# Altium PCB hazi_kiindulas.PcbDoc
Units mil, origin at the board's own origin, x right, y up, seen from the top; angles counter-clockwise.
Board outline 3628.74 x 2378.74 mil, 2 copper layers (Top Layer, Bottom Layer); 31 components, 39 nets, 235 pads, 42 vias.
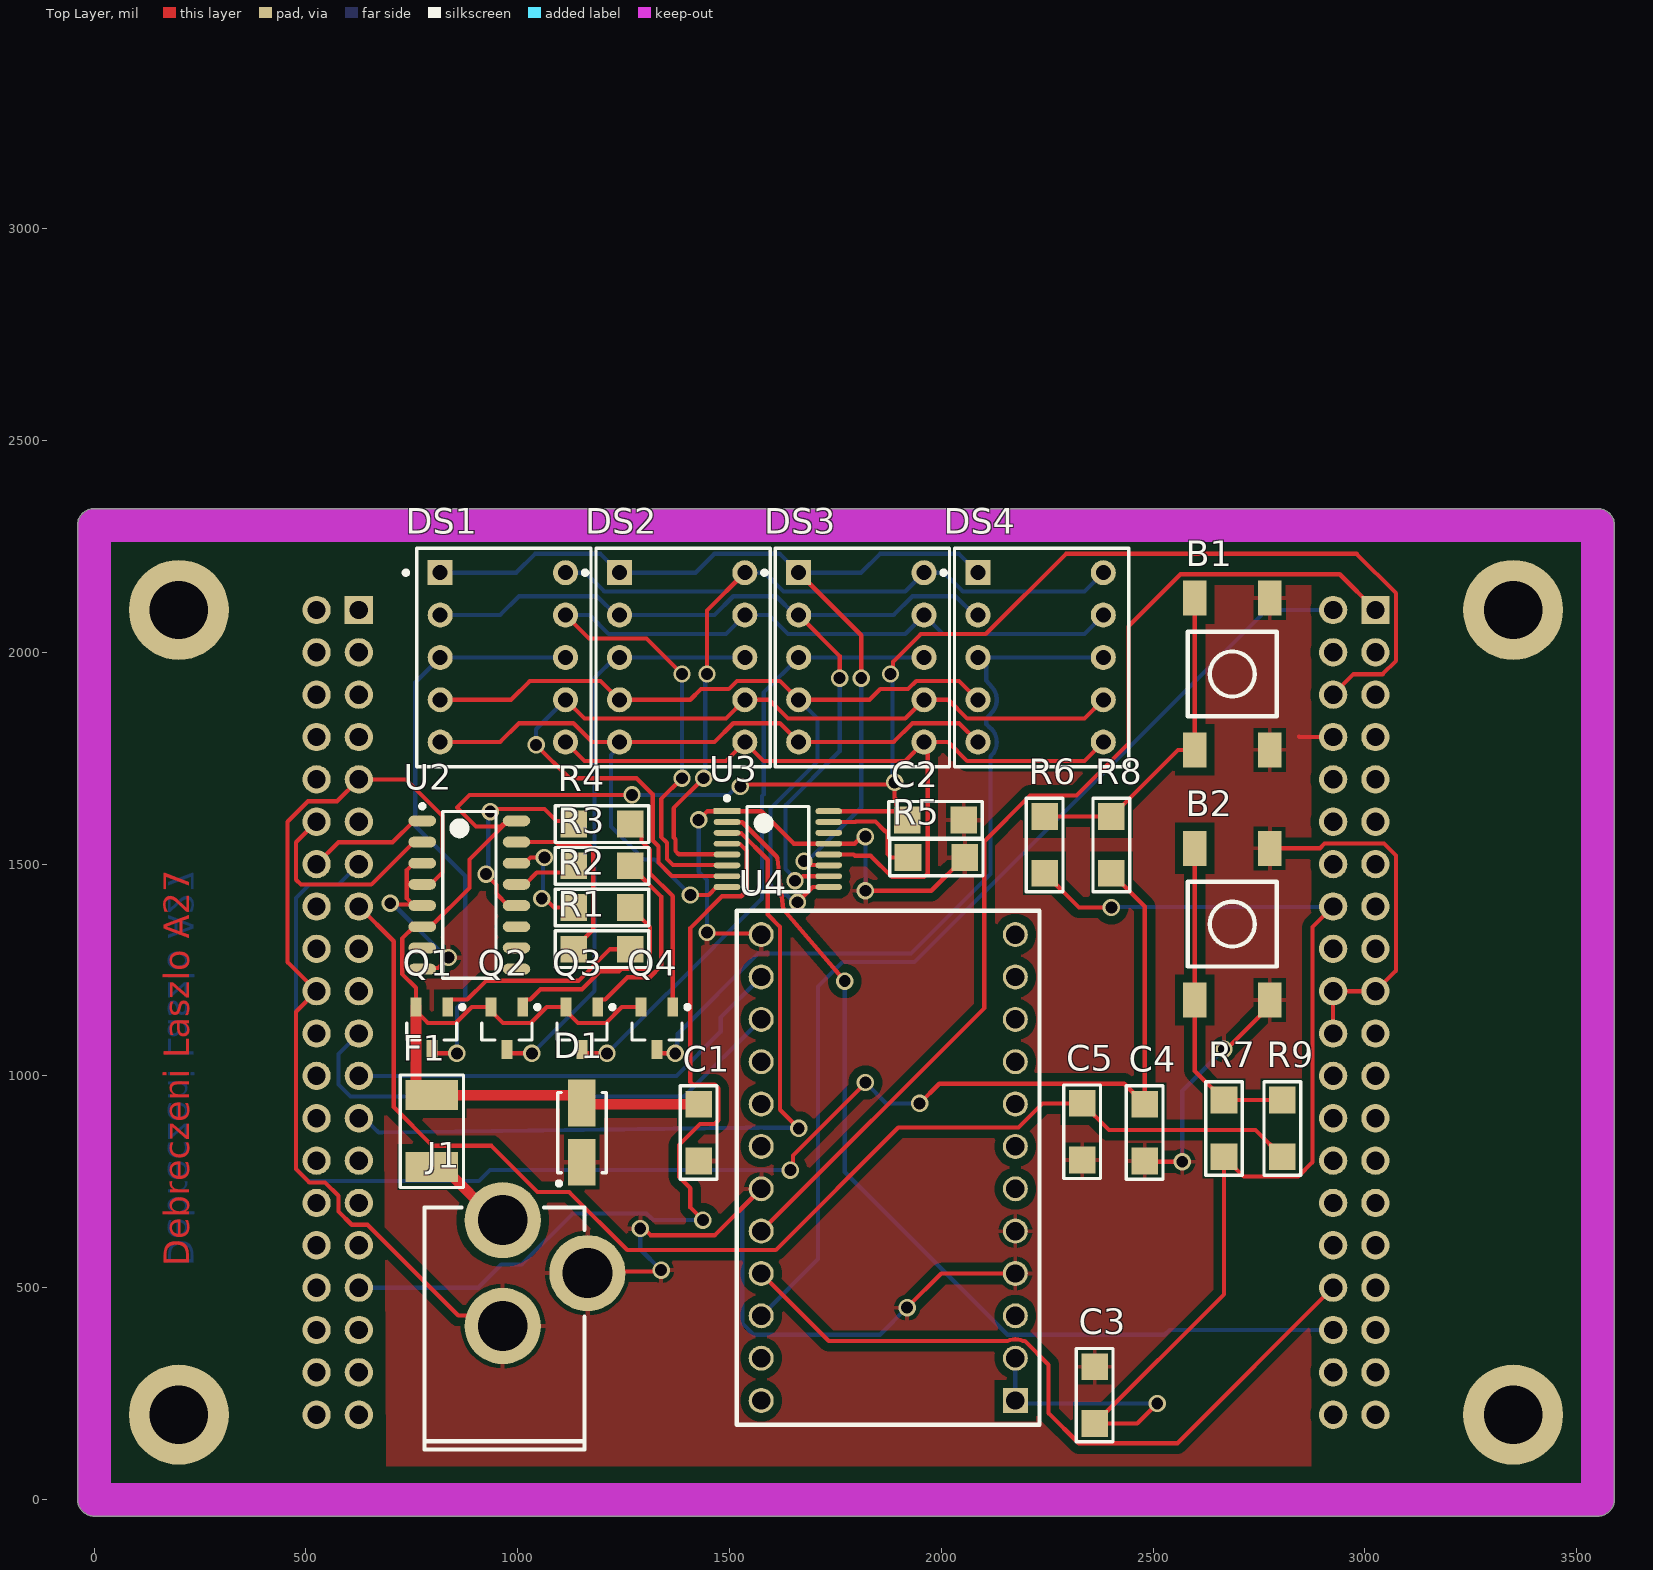
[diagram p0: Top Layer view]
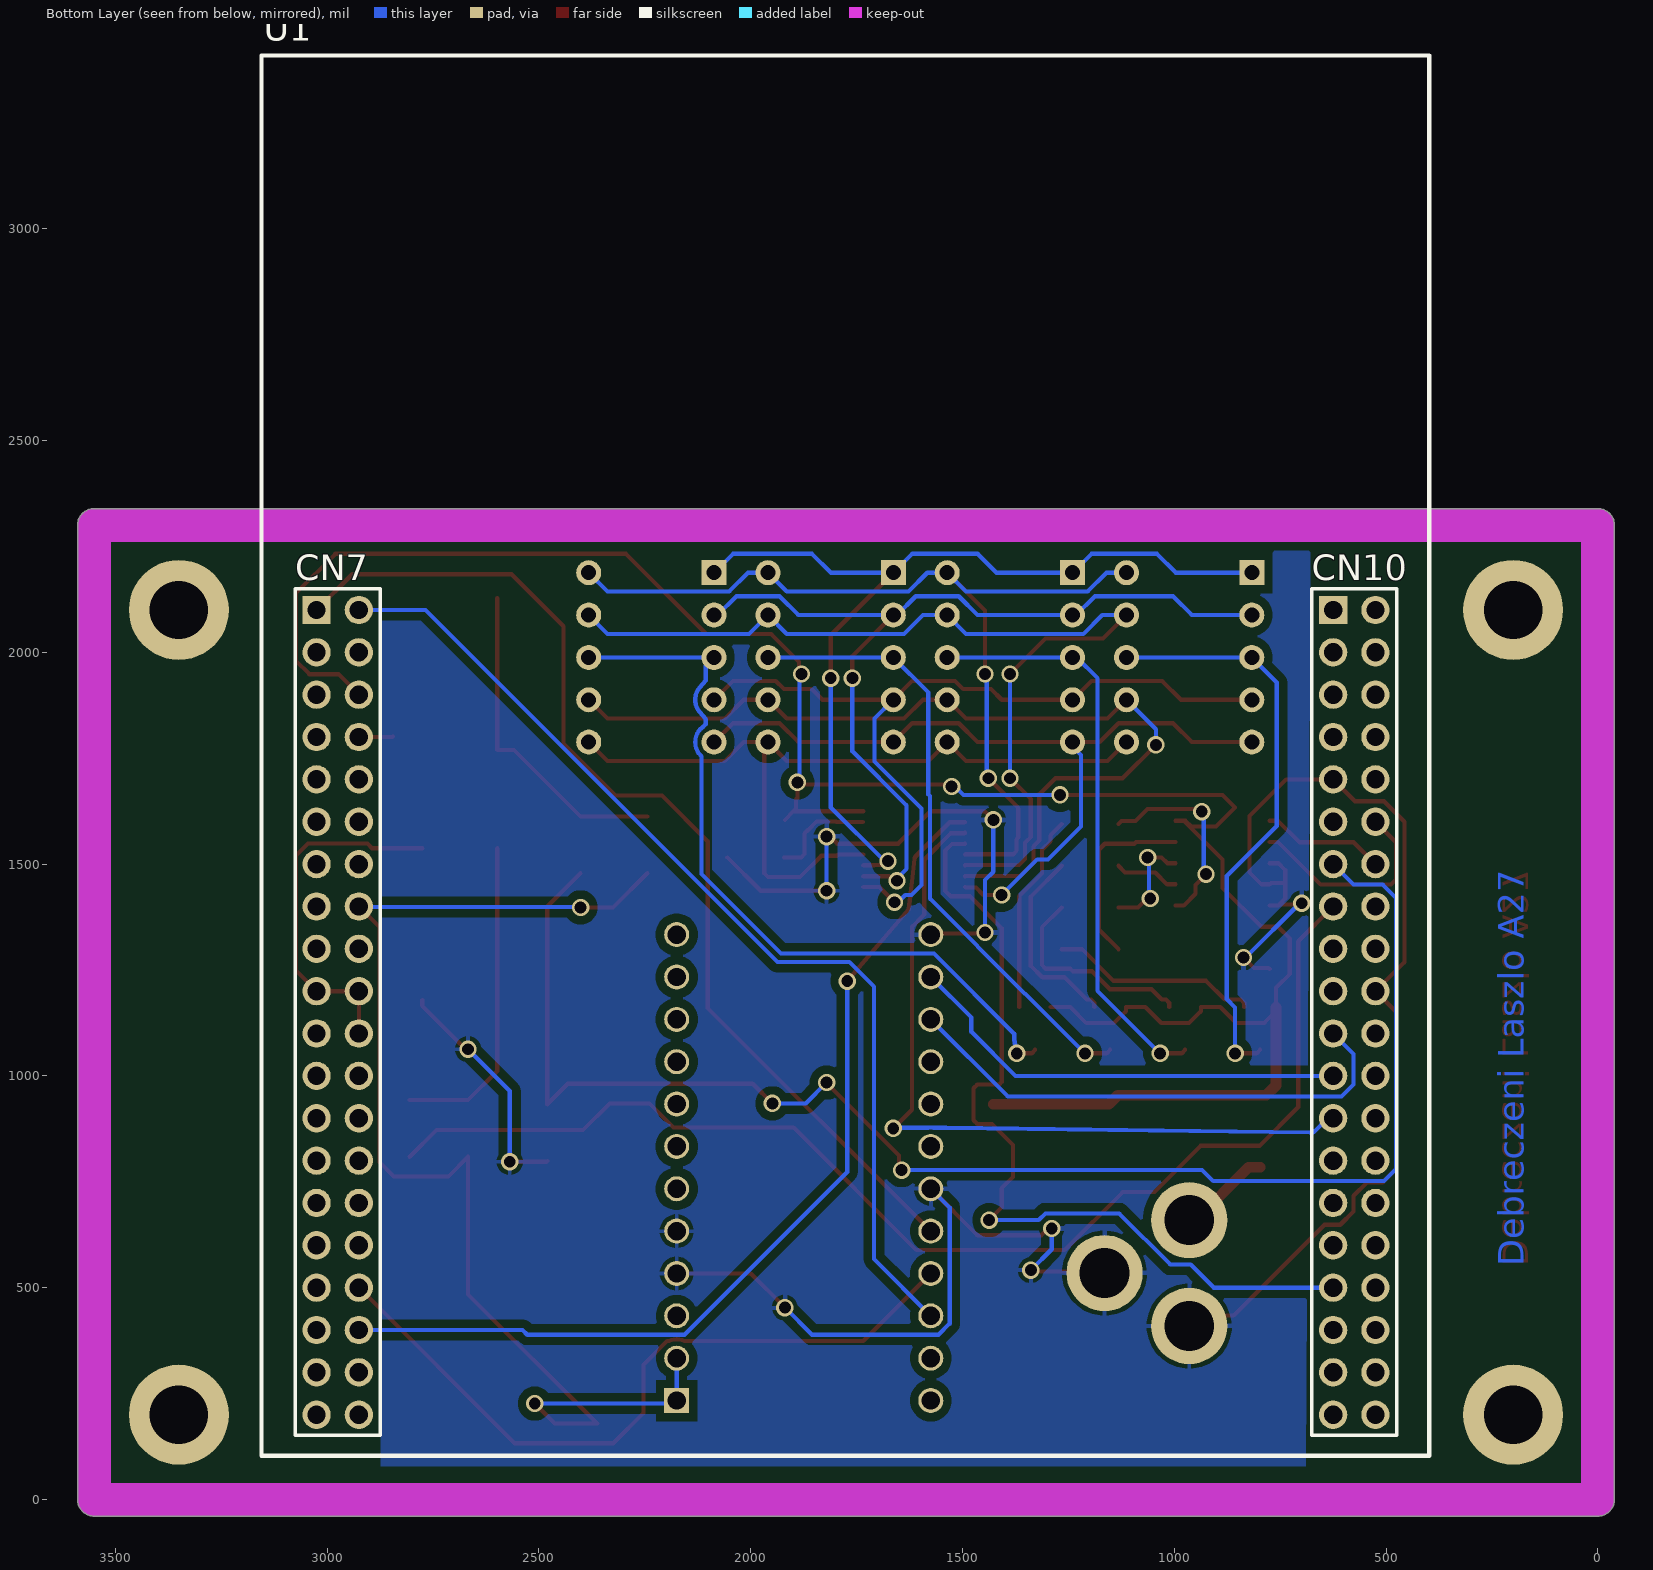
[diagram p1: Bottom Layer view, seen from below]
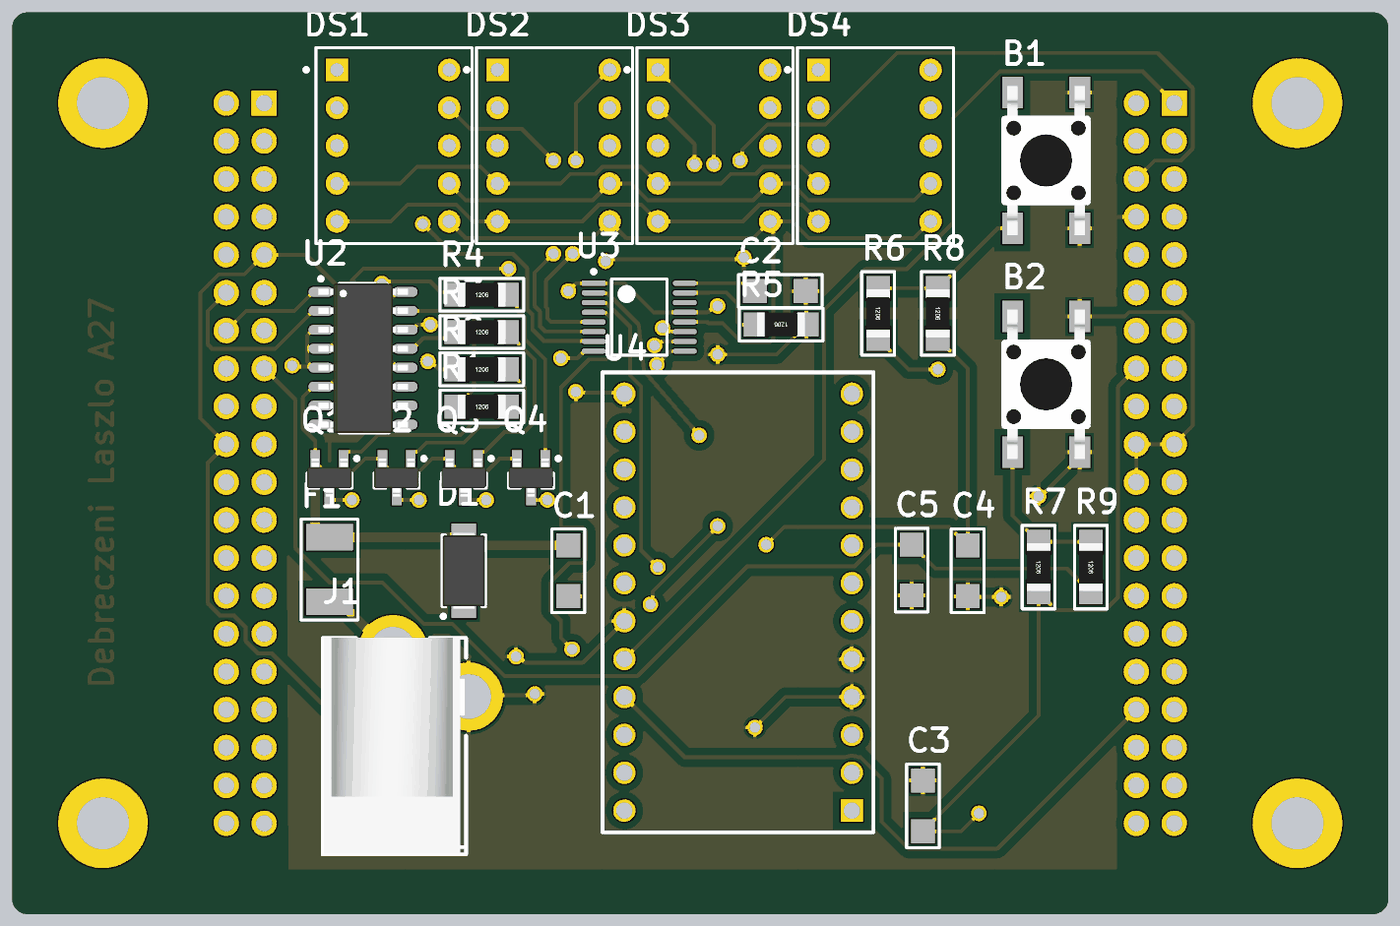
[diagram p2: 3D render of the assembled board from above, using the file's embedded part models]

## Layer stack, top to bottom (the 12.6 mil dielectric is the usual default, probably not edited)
Top Solder: solder mask 0.4, Solder Resist, Dk 3.5
Top Layer: signal copper 1.4
Dielectric 1: dielectric 12.6, FR-4, Dk 4.8
Bottom Layer: signal copper 1.4
Bottom Solder: solder mask 0.4, Solder Resist, Dk 3.5

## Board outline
-39.37,2300 cw(c0,2300) 0,2339.37 3550,2339.37 cw(c3550,2300) 3589.37,2300 3589.37,0 cw(c3550,0) 3550,-39.37 0,-39.37 cw(c0,0) -39.37,0

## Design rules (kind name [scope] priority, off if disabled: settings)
Clearance [All] p1: gap=10 ignorepadtopadclearanceinfootprint=FALSE except(20: Arc-Poly Track-Poly SMDPad-Poly THPad-Poly Via-Poly Fill-Poly Poly-Poly)
HoleSize [IsVia] p1: absolutevalues=TRUE maxlimit=196.85 minlimit=28 maxpercent=80.000 minpercent=20.000
PolygonConnect [All] p1: connectstyle=Relief reliefconductorwidth=10 reliefentries=4 polygonreliefangle="90 Angle" airgapwidth=10
RoutingVias [All] p1: holewidth=28 width=41 viastyle="Through Hole" minholewidth=28 minwidth=41 maxholewidth=28 maxwidth=41
SolderMaskExpansion [All] p1: expansion=4 istentingtop=FALSE
UnRoutedNet [All] p1: checkbadconnections=TRUE
Width [All] p1: maxlimit=100 minlimit=10 preferedwidth=10
28 further rules are at their usual default settings.

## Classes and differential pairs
component class Pushbuttons: B1 B2 C4 C5 R6 R7 R8 R9
component class Power: D1 F1 J1
component class Acceleration_module: C3 U4
component class 7segment: C1 C2 DS1 DS2 DS3 DS4 Q1 Q2 Q3 Q4 R1 R2 R3 R4 R5 U2 U3
component class Nucleo: U1

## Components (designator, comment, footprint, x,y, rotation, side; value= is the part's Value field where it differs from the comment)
B1 "Button" FP_BTN_SMD 2687.01,1948.82 r0 top
B2 "Button" FP_BTN_SMD 2687.01,1358.27 r0 top
C1 "100nF" FP_1206_CAP_125 1427.17,866.14 r90 top
C2 "100nF" FP_1206_CAP_125 1986.22,1604.33 r180 top
C3 "100nF" FP_1206_CAP_125 2362.2,246.06 r270 top
C4 "100nF" FP_1206_CAP_125 2480.31,866.14 r90 top
C5 "100nF" FP_1206_CAP_125 2332.68,868.11 r90 top
D1 "Unidir suppressor diode" DIOM4426X23M 1151.57,866.14 r90 top
DS1 "7SEG Red-CA" FP_7SEG 964.57,1988.19 r0 top
DS2 "7SEG Red-CA" FP_7SEG 1387.8,1988.19 r0 top
DS3 "7SEG Red-CA" FP_7SEG 1811.02,1988.19 r0 top
DS4 "7SEG Red-CA" FP_7SEG 2234.25,1988.19 r0 top
F1 "Fuse" FP_MULTIFUSE 797.24,784.72 r90 top
J1 "2.xmm" FP_DC_TAP_ANYA 964.57,659.45 r180 top
Q1 "BC807-25" SOT95P240X115-3M 797.24,1112.2 r270 top
Q2 "BC807-25" SOT95P240X115-3M 974.41,1112.2 r270 top
Q3 "BC807-25" SOT95P240X115-3M 1151.57,1112.2 r270 top
Q4 "BC807-25" SOT95P240X115-3M 1328.74,1112.2 r270 top
R1 "10K" FP_1206_RES 1198.82,1299.21 r0 top
R2 "10K" FP_1206_RES 1198.82,1397.64 r0 top
R3 "10K" FP_1206_RES 1198.82,1496.06 r0 top
R4 "10K" FP_1206_RES 1198.82,1594.49 r0 top
R5 "1K" FP_1206_RES 1988.19,1515.75 r180 top
R6 "100K" FP_1206_RES 2244.09,1545.28 r270 top
R7 "100K" FP_1206_RES 2667.32,875.98 r270 top
R8 "10K" FP_1206_RES 2401.57,1545.28 r270 top
R9 "10K" FP_1206_RES 2805.12,875.98 r270 top
U1 "NUCLEO-F446RE" FP_NUCLEO-64 3025,2100 r180 bottom locked
U2 "SN74HCT138DR" SOIC127P600X175-16M 885.83,1427.17 r0 top
U3 "STP08CP05TTR" TSOP65P640X120-16M 1614.17,1535.43 r0 top
U4 "MKI160V1" FP_DIL24 2174.8,233.46 r0 top

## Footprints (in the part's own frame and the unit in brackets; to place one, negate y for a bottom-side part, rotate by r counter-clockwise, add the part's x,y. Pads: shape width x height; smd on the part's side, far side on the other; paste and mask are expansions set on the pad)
DIOM4426X23M [mm] "Molded Diode, 2-Leads, Body 4,40x2,62mm, IPC Low Density"
  rect 2.8x1.65 smd: 1(-1.775,0) 2(1.775,0)
  silkscreen extent -3.17,-1.45 2.4,1.5, body extent -2.6,-1.42 2.6,1.42, height 2.3
FP_7SEG [mm] "LED, 7-Segment Display, 7.62 mm, RHD; 10 Leads; Row Space 5.08 mm; Pitch 2.54 mm"
  rect 1.5x1.5 hole 0.9: 1(-3.75,5.075)
  round 1.5 hole 0.9: 2(-3.75,2.535) 3(-3.75,-0.005) 4(-3.75,-2.545) 5(-3.75,-5.085) 6(3.765,-5.085) 7(3.765,-2.545) 8(3.765,-0.005) 9(3.765,2.535) 10(3.765,5.075)
  silkscreen extent -5.93,-6.56 5.29,6.54, body extent -5.16,-6.56 5.29,6.54, height 6.34
FP_1206_CAP_125 [mm] "1206 kapacitás 1.25 mm"
  rect 1.6x1.6 smd: 1(-1.7,0) 2(1.7,0)
  silkscreen extent -2.8,-1.1 2.8,1.1, body extent -1.52,-0.79 1.58,0.79, height 1.25
FP_1206_RES [mm] "1206 ellenállás"
  rect 1.6x1.6 smd: 1(-1.7,0) 2(1.7,0)
  silkscreen extent -2.8,-1.1 2.8,1.1, body extent -1.6,-0.8 1.6,0.8, height 0.62
FP_BTN_SMD [mm] "SMD Push Button 6x6mm"
  rect 1.4x2.1 smd: 1(2.25,4.55) 2(2.25,-4.55) 3(-2.25,4.55) 4(-2.25,-4.55)
  silkscreen extent -2.67,-2.54 2.67,2.54, body extent -3,-5 3,5, height 5.1
FP_DC_TAP_ANYA [mil] "DC HEBA25 TÁPFESZÜLTSÉG ALJZAT ZÁRT, NYÁKBA 90°"
  round 180 hole 118: 1(0,0) 2(0,250) 3(-200,125)
  silkscreen extent -193,-30 185,541, body extent -190,-31 183,539, height 440
FP_DIL24 [mm] "DIL24"
  rect 1.5x1.5 hole 1.1: 1(0,0)
  round 1.5 hole 1.1: 2(0,2.54) 3(0,5.08) 4(0,7.62) 5(0,10.16) 6(0,12.7) 7(0,15.24) 8(0,17.78) 9(0,20.32) 10(0,22.86) 11(0,25.4) 12(0,27.94) 13(-15.24,27.94) 14(-15.24,25.4) 15(-15.24,22.86) 16(-15.24,20.32) 17(-15.24,17.78) 18(-15.24,15.24) 19(-15.24,12.7) 20(-15.24,10.16) 21(-15.24,7.62) 22(-15.24,5.08) 23(-15.24,2.54) 24(-15.24,0)
  silkscreen extent -16.7,-1.45 1.45,29.38, body extent -16.52,-1.28 1.28,29.21, height 4.86
FP_MULTIFUSE [mm] "POLYFUSE SMD 1812"
  rect 1.78x3.15 smd: 1(0,0) 2(4.318,0)
  silkscreen extent -1.22,-1.9 5.53,1.9, body extent -0.12,-1.71 4.57,1.71, height 1
FP_NUCLEO-64 [mm]
  round 1.7 hole 1.1: 0(0,-48.26) 0(2.54,-48.26) 0(60.96,-48.26) 0(63.5,-48.26) 2(2.54,0) 3(0,-2.54) 4(2.54,-2.54) 5(0,-5.08) 6(2.54,-5.08) 7(0,-7.62) 8(2.54,-7.62) 9(0,-10.16) 10(2.54,-10.16) 11(0,-12.7) 12(2.54,-12.7) 13(0,-15.24) 14(2.54,-15.24) 15(0,-17.78) 16(2.54,-17.78) 17(0,-20.32) 18(2.54,-20.32) 19(0,-22.86) 20(2.54,-22.86) 21(0,-25.4) 22(2.54,-25.4) 23(0,-27.94) 24(2.54,-27.94) 25(0,-30.48) 26(2.54,-30.48) 27(0,-33.02) 28(2.54,-33.02) 29(0,-35.56) 30(2.54,-35.56) 31(0,-38.1) 32(2.54,-38.1) 33(0,-40.64) 34(2.54,-40.64) 35(0,-43.18) 36(2.54,-43.18) 37(0,-45.72) 38(2.54,-45.72) 40(63.5,0) 41(60.96,-2.54) 42(63.5,-2.54) 43(60.96,-5.08) 44(63.5,-5.08) 45(60.96,-7.62) 46(63.5,-7.62) 47(60.96,-10.16) 48(63.5,-10.16) 49(60.96,-12.7) 50(63.5,-12.7) 51(60.96,-15.24) 52(63.5,-15.24) 53(60.96,-17.78) 54(63.5,-17.78) 55(60.96,-20.32) 56(63.5,-20.32) 57(60.96,-22.86) 58(63.5,-22.86) 59(60.96,-25.4) 60(63.5,-25.4) 61(60.96,-27.94) 62(63.5,-27.94) 63(60.96,-30.48) 64(63.5,-30.48) 65(60.96,-33.02) 66(63.5,-33.02) 67(60.96,-35.56) 68(63.5,-35.56) 69(60.96,-38.1) 70(63.5,-38.1) 71(60.96,-40.64) 72(63.5,-40.64) 73(60.96,-43.18) 74(63.5,-43.18) 75(60.96,-45.72) 76(63.5,-45.72)
  rect 1.7x1.7 hole 1.1: 1(0,0) 39(60.96,0)
  silkscreen extent -3.3,-50.72 66.72,33.25, body extent -3.3,-50.72 66.72,33.25, height 11
SOIC127P600X175-16M [mm] "SOIC, 16-Leads, Body 9,90x3,90mm, Pitch 1,27mm, IPC Low Density"
  oval 1.65x0.65 smd: 1(-2.825,4.445) 2(-2.825,3.175) 3(-2.825,1.905) 4(-2.825,0.635) 5(-2.825,-0.635) 6(-2.825,-1.905) 7(-2.825,-3.175) 8(-2.825,-4.445) 9(2.825,-4.445) 10(2.825,-3.175) 11(2.825,-1.905) 12(2.825,-0.635) 13(2.825,0.635) 14(2.825,1.905) 15(2.825,3.175) 16(2.825,4.445)
  silkscreen extent -2.95,-5 1.6,5.44, body extent -3,-5 3,5, height 1.75
SOT95P240X115-3M [mm] "SOT23, 3-Leads, Body 2,90x2,40mm, Pitch 0,95mm, IPC Low Density"
  rect 1.15x0.65 smd: 1(-1.275,0.95) 2(-1.275,-0.95) 3(1.275,0)
  silkscreen extent -1.4,-1.5 0.7,1.95, body extent -1.28,-1.5 1.28,1.5, height 1.15
TSOP65P640X120-16M [mm] "TSOP, 16-Leads, Body 5,00x4,40mm, Pitch 0,65mm, IPC Low Density"
  rect 1.6x0.35 smd: 1(-3.05,2.275)
  oval 1.6x0.35 smd: 2(-3.05,1.625) 3(-3.05,0.975) 4(-3.05,0.325) 5(-3.05,-0.325) 6(-3.05,-0.975) 7(-3.05,-1.625) 8(-3.05,-2.275) 9(3.05,-2.275) 10(3.05,-1.625) 11(3.05,-0.975) 12(3.05,-0.325) 13(3.05,0.325) 14(3.05,0.975) 15(3.05,1.625) 16(3.05,2.275)
  silkscreen extent -3.17,-2.55 1.85,3.17, body extent -2.25,-2.55 2.25,2.55, height 1.2

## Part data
B1 B2: library part "Button 4P", "Push button"
C1 C2 C3 C4 C5: library part CAP, "Capacitor", Tolerance=10%, Voltage=50V
D1: library part "Suppressor diode", "Suppressor diode for transients"
DS1 DS2 DS3 DS4: "7-Segment Display: CA, RH DP", Colour="High Efficiency Red (HER)"
J1: library part DC_TAP_ANYA, "2.xmm DC HEBA25 TÁPFESZÜLTSÉG ALJZAT ZÁRT, NYÁKBA 90°"
Q1 Q2 Q3 Q4: "PNP General-purpose Transistor"
R1 R2 R3 R4 R5 R6 R7 R8 R9: library part RES, "Resistor", Power=0.25W, Tolerance=5%
U2: "3-line to 8-line decoder"
U3: "Low voltage, low current power 8-bit shift register"
U4: "LSM6DS3 inertial module adapter"

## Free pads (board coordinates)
  round 236.22 hole 137.8: ""(200,200) ""(200,2100) ""(3350,200) ""(3350,2100)

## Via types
v1: diameter 41, hole 28, Top Layer to Bottom Layer, 42 vias

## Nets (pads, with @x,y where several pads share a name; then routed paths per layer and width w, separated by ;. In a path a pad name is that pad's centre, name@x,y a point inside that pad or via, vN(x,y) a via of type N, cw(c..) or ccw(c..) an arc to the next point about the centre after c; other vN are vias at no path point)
+3.3V: C3.2 R6.2 R7.2 U1.16 U4.1 U4.2 | length 2943
  Top Layer w10: R6.2 2324.8,1397.64 v1(2401.57,1397.64) ; v1(2509.84,226.38) 2462.6,179.13 C3.2 2667.32,484.25 R7.2 2713.82,762.56 2842.83,762.56 2876.54,796.27 2876.54,1351.54 U1.16
  Bottom Layer w10: U4.2 U4.1 2181.89,226.38 v1(2509.84,226.38) ; v1(2401.57,1397.64) 2402.76,1398.82 2923.82,1398.82 U1.16
+5V: C1.2 C2.2 D1.2 F1.2 Q1.2 Q2.2 Q3.2 Q4.2 U1.6 U2.6 U2.16 U3.16 | length 5535.8
  Top Layer w10: Q1.2@759.84,1152.56 767.64,1144.76 767.73,1144.76 787.73,1124.76 853.65,1124.76 891.29,1162.4 Q2.2 937.01,1152.56 944.8,1144.76 944.89,1144.76 964.89,1124.76 1030.82,1124.76 1068.46,1162.4 Q3.2 1114.17,1152.56 1121.97,1144.76 1122.06,1144.76 1142.06,1124.76 1207.98,1124.76 1245.62,1162.4 Q4.2 ; Q1.2 759.84,1207.94 727.13,1240.65 727.13,1324.37 754.92,1352.17 U2.6 794.29,1352.17 885.83,1443.7 885.83,1510.63 U2.16@977.36,1602.17 ; U2.16 U2.16@977.36,1602.17 ; v1(1269.69,1663.39) 885.83,1663.39 856.3,1633.86 901.64,1588.52 959.49,1588.52 973.14,1602.17 U2.16@977.36,1602.17 ; v1(1525.59,1683.07) 1530.51,1687.99 1884.84,1687.99 v1(1889.76,1692.91) 1889.76,1656.23 1892.8,1653.19 1892.8,1630.83 C2.2@1898.62,1625 ; U3.16 C2.2@1898.62,1625 ; v1(1879.92,1948.82) 1885.85,1954.75 1885.85,1977.56 1951.75,2043.46 2105.06,2043.46 2294.11,2232.52 2980.62,2232.52 3073.46,2139.68 3073.46,1979.93 3042,1948.46 2973.46,1948.46 U1.6 ; C2.2 C2.2@1898.62,1625
  Top Layer w25: Q1.2 759.84,1152.56 759.84,977.26 782.38,954.72 F1.2 1132.87,954.72 D1.2 1154.53,933.07 C1.2
  Bottom Layer w10: v1(1269.69,1663.39) 1497.52,1663.39 1517.2,1683.07 v1(1525.59,1683.07) ; v1(1879.92,1948.82) 1884.84,1943.9 1884.84,1697.83 v1(1889.76,1692.91)
D1: DS1.10 DS2.10 DS3.10 DS4.10 U3.5 | length 2233.7
  Top Layer w10: v1(1438.8,1702.76) 1368.11,1632.07 1368.11,1562.76 1372.24,1558.62 1372.24,1531.3 1380.18,1523.36 1493.37,1523.36 U3.5 ; v1(1446.85,1948.82) 1446.85,2098.82 DS2.10
  Bottom Layer w10: DS1.10 1159.89,2187.99 1204.42,2143.46 1491.5,2143.46 DS2.10 1583.12,2187.99 1627.64,2143.46 1914.72,2143.46 DS3.10 2006.35,2187.99 2050.87,2143.46 2337.95,2143.46 DS4.10 ; v1(1438.8,1702.76) 1442.82,1706.78 1442.82,1944.79 v1(1446.85,1948.82)
D2: DS1.9 DS2.9 DS3.9 DS4.9 U3.6 | length 2323.9
  Top Layer w10: DS1.9 1168.27,2032.52 1304.09,2032.52 v1(1387.8,1948.82) ; v1(1387.8,1702.76) 1338.58,1653.54 1338.58,1564 1352.24,1550.34 1352.24,1511.93 1366.4,1497.77 1493.37,1497.77 U3.6
  Bottom Layer w10: DS1.9 1170.07,2087.99 1214.6,2043.46 1491.5,2043.46 DS2.9 1593.3,2087.99 1637.83,2043.46 1914.72,2043.46 DS3.9 2003.78,2043.46 2337.95,2043.46 DS4.9 ; v1(1387.8,1702.76) v1(1387.8,1948.82)
D3: DS1.7 DS2.7 DS3.7 DS4.7 U3.7 | length 2181.2
  Top Layer w10: v1(1043.31,1781.5) 1122.05,1702.76 1280.52,1702.76 1318.58,1664.69 1318.58,1555.72 1332.24,1542.06 1332.24,1503.64 1363.71,1472.18 1493.37,1472.18 U3.7 ; DS1.7 1157.32,1843.46 1491.5,1843.46 DS2.7 1593.3,1887.99 1637.83,1843.46 1914.72,1843.46 DS3.7 2016.53,1887.99 2061.06,1843.46 2337.95,1843.46 DS4.7
  Bottom Layer w10: v1(1043.31,1781.5) 1043.31,1818.5 DS1.7
D4: DS1.5 DS2.5 DS3.5 DS4.5 U3.8 | length 1936
  Top Layer w10: DS1.5 958.46,1787.99 1002.99,1832.52 1131.24,1832.52 1175.77,1787.99 DS2.5 1464.31,1787.99 1508.84,1832.52 1618.86,1832.52 DS3.5 1887.54,1787.99 1932.06,1832.52 2042.09,1832.52 DS4.5 ; v1(1407.48,1427.17) 1450.79,1427.17 1468.25,1444.63 1492.86,1444.63 U3.8
  Bottom Layer w10: DS2.5 1240.16,1777.29 1220.47,1757.61 1220.47,1588.79 1298.32,1510.94 1323.7,1510.94 v1(1407.48,1427.17)
D5: DS1.4 DS2.4 DS3.4 DS4.4 U3.9 | length 2051.1
  Top Layer w10: DS1.4 984.02,1887.99 1028.54,1932.52 1195.63,1932.52 DS2.4 1407.24,1887.99 1432.57,1913.32 1498.38,1913.32 1517.58,1932.52 1618.86,1932.52 DS3.4 1830.47,1887.99 1855.8,1913.32 1921.61,1913.32 1940.81,1932.52 2042.09,1932.52 DS4.4 ; v1(1660.65,1409.94) 1696.57,1445.87 U3.9
  Bottom Layer w10: v1(1660.65,1409.94) 1652.26,1409.94 1635.07,1427.13 1620.56,1427.13 1596.93,1450.76 1596.93,1631.52 1707.91,1742.51 1707.91,1843.46 DS3.4
D6: DS1.2 DS2.2 DS3.2 DS4.2 U3.10 | length 2194.7
  Top Layer w10: v1(1654.43,1460.56) 1662.82,1460.56 1673.66,1471.4 1732.86,1471.4 1733.53,1470.73 U3.10 ; DS3.2 1760.02,1991.35 v1(1760.02,1938.98)
  Bottom Layer w10: DS1.2 958.46,2087.99 1002.99,2132.52 1187.08,2132.52 1231.6,2087.99 1464.31,2087.99 1508.84,2132.52 1610.31,2132.52 1654.83,2087.99 DS3.2 1887.54,2087.99 1932.06,2132.52 2033.53,2132.52 2078.06,2087.99 DS4.2 ; v1(1654.43,1460.56) 1654.43,1466.76 1632.43,1488.76 1632.43,1638.74 1760.02,1766.33 v1(1760.02,1938.98)
D7: DS1.1 DS2.1 DS3.1 DS4.1 U3.11 | length 2279.9
  Top Layer w10: DS3.1 1811.02,2040.35 v1(1811.02,1938.98) ; v1@1681.48,1501.15 v1(1675.73,1506.9) 1684.12,1506.9 1693.25,1497.77 1733.53,1497.77 U3.11 U3.11@1708.62,1497.05
  Bottom Layer w10: DS1.1 996.28,2187.99 1040.81,2232.52 1195.63,2232.52 DS2.1 1419.51,2187.99 1464.04,2232.52 1618.86,2232.52 DS3.1 1810.54,2187.99 1855.07,2232.52 2042.09,2232.52 DS4.1 ; v1(1675.73,1506.9) 1684.07,1506.9 1811.02,1633.86 v1(1811.02,1938.98)
D8: DS1.6 DS2.6 DS3.6 DS4.6 U3.12 | length 1953.1
  Top Layer w10: DS1.6 1157.32,1743.46 1491.5,1743.46 DS2.6 1580.55,1743.46 1914.72,1743.46 DS3.6 ; U3.12 1793.3,1522.64 1796.32,1519.62 1833.18,1519.62 1883.55,1469.25 1958.97,1469.25 1967.76,1478.04 1967.76,1779.49 DS3.6 ; DS4.6 2337.95,1743.46 2061.06,1743.46 2016.53,1787.99 DS3.6
GND: B1.1 B1.2 B2.1 B2.2 C1.1 C2.1 C3.1 C4.1 C5.1 D1.1 J1.2 J1.3 R5.1 U1.8 U1.19 U1.20 U1.22 U1.47 U1.58 U2.3 U2.4 U2.5 U2.8 U3.1 U3.13 U4.4 U4.5 U4.13 U4.19 | length 7147.8
  Top Layer w10: v1(698.82,1407.48) 701.48,1404.82 U2.5@750.69,1404.82 ; U2.8 776.87,1254.43 811.51,1254.43 v1(836.61,1279.53) ; U2.5 753.35,1402.17 U2.5@750.69,1404.82 ; U2.3 754.13,1502.17 738.19,1486.22 738.19,1458.02 ; J1.2 J1.2@960.63,413.39 ; J1.2@972.54,413.39 J1.2@960.63,413.39 ; J1.3@1097.54,538.39 J1.3@1135.04,538.39 ; J1.3 1168.01,537.89 1335.14,537.89 v1(1338.58,541.34) ; v1(1289.37,639.76) 1297.76,639.76 1313.57,623.95 1465.29,623.95 U4.19 ; v1(1427.17,1604.33) 1447.83,1625 U3.1 1574.91,1625 1651.69,1548.23 U3.13 1795.75,1548.23 1812.48,1564.96 v1(1820.87,1564.96) ; v1(1446.85,1338.58) 1449.41,1336.02 1572.24,1336.02 U4.13 ; v1(1820.87,1437.01) 1976.38,1437.01 R5.1 ; v1(1919.29,452.76) 2000,533.46 U4.4 ; C4.1 2482.28,797.24 v1(2568.9,797.24) ; v1(2667.32,1062.99) 2673.23,1062.99 2775.59,1165.35 B2.2 ; B2.1 2893.86,1537.4 2904.93,1548.46 3045.07,1548.46 3073.46,1520.07 3073.46,1248.46 U1.19 U1.20 U1.22 ; 2844.49,1801.18 2845.67,1800 U1.8 ; 738.19,1458.02 738.19,1418.69 749.73,1407.16 749.73,1405.79 U2.5@750.69,1404.82 ; 738.19,1458.02 741.06,1455.15 771.62,1455.15 U2.4 794.29,1452.17 822.09,1479.96 822.09,1613.68 735.77,1700 U1.47 573.46,1648.46 504.93,1648.46 456.54,1600.07 456.54,1268.46 U1.58 476.54,1151.54 476.54,779.93 508,748.46 545.07,748.46 576.54,717 576.54,679.93 608,648.46 645.07,648.46 859.57,433.97 940.04,433.97 J1.2@960.63,413.39
  Bottom Layer w10: v1(698.82,1407.48) 703.74,1407.48 831.69,1279.53 v1(836.61,1279.53) ; v1(1289.37,639.76) 1289.37,590.55 v1(1338.58,541.34) ; v1(1427.17,1604.33) 1427.17,1482.03 1446.85,1462.34 v1(1446.85,1338.58) ; U4.19 1530.28,688.94 1530.28,415.02 1556.36,388.94 1855.47,388.94 v1(1919.29,452.76) ; v1(1820.87,1437.01) v1(1820.87,1564.96) ; v1(2568.9,797.24) 2568.9,964.57 v1(2667.32,1062.99)
NetB1_3: B1.3 B1.4 R6.1 R8.1 | length 777.8
  Top Layer w10: R6.1 R8.1 2559.06,1769.68 B1.4 B1.3
NetB2_3: B2.3 B2.4 R7.1 R9.1 | length 760.8
  Top Layer w10: B2.3 B2.4 2598.43,1011.81 R7.1 R9.1
NetC4_2: C4.2 R8.2 U1.51 | length 3588.9
  Top Layer w10: v1(1643.7,777.56) 1649.63,783.49 1649.63,812.03 1820.87,983.26 v1(1820.87,984.25) ; v1(1948.82,935.04) 1995.32,981.54 2431.85,981.54 C4.2 2480.31,1399.61 R8.2
  Bottom Layer w10: U1.51 576.54,1451.54 508,1451.54 476.54,1420.07 476.54,779.93 504.93,751.54 908.16,751.54 934.62,777.99 1643.27,777.99 v1(1643.7,777.56) ; v1(1820.87,984.25) 1870.08,935.04 v1(1948.82,935.04)
NetC5_2: C5.2 R9.2 U1.53 | length 2940.8
  Top Layer w10: U1.53 707.13,1317.87 707.13,926.58 798.94,834.76 937.74,834.76 1046.37,726.14 1121.37,726.14 1258.57,588.94 1609.32,588.94 1898.38,877.99 2182.3,877.99 2239.35,935.04 C5.2 2395.67,872.05 2742.13,872.05 R9.2
NetDS1_3: DS1.3 DS1.8 Q1.3 | length 1375.6
  Top Layer w10: Q1.3 797.24,1060.94 805.04,1053.15 v1(856.3,1053.15)
  Bottom Layer w10: v1(856.3,1053.15) 856.3,1161.64 875.98,1181.33 875.98,1471.8 757.87,1589.91 757.87,1928.94 DS1.3 DS1.8
NetDS2_3: DS2.3 DS2.8 Q2.3 | length 1385.6
  Top Layer w10: Q2.3 974.41,1060.94 982.2,1053.15 v1(1033.46,1053.15)
  Bottom Layer w10: v1(1033.46,1053.15) 1181.1,1200.79 1181.1,1938.98 1230.12,1987.99 DS2.3 DS2.8
NetDS3_3: DS3.3 DS3.8 Q3.3 | length 1482.2
  Top Layer w10: Q3.3 1151.57,1060.94 1159.37,1053.15 v1(1210.63,1053.15)
  Bottom Layer w10: v1(1210.63,1053.15) 1351.06,1193.58 1352.05,1193.58 1576.93,1418.46 1576.93,1660.49 1580.55,1664.11 1580.55,1905.16 DS3.3 DS3.8
NetDS4_3: DS4.3 DS4.8 Q4.3 | length 1832.9
  Top Layer w10: Q4.3 1328.74,1060.94 1336.54,1053.15 v1(1371.98,1053.15)
  Bottom Layer w10: v1(1371.98,1053.15) 1377.95,1085.37 1377.95,1099.59 1567.3,1288.94 1928.7,1288.94 2116.14,1476.38 2116.14,1754.57 2117.2,1755.63 ccw(c2086.61,1787.99) 2112.27,1824.39 cw(c2118.13,1832.49) 2111.51,1824.99 2108.36,1828.14 2106.3,1830.25 2106.3,1833.97 2106.3,1842.25 2120.66,1859.3 ccw(c2086.61,1887.99) 2120.66,1916.69 2106.3,1933.73 2106.3,1968.31 2103.37,1971.24 DS4.3 DS4.8
NetF1_1: F1.1 J1.1 | length 219.2
  Top Layer w25: F1.1 824.21,784.72 949.49,659.45 J1.1
NetQ1_1: Q1.1 R1.2 | length 493.5
  Top Layer w10: Q1.1 834.65,1172.24 842.44,1180.04 880.65,1180.04 924.98,1224.37 1143.22,1224.37 1218.06,1299.21 R1.2
NetQ2_1: Q2.1 R2.2 | length 502.6
  Top Layer w10: Q2.1 1011.81,1172.24 1019.61,1180.04 1029.45,1180.04 1053.78,1204.37 1151.51,1204.37 1194.04,1246.9 1239.34,1246.9 1245.15,1252.72 1303.46,1252.72 1312.24,1261.5 1312.24,1351.14 R2.2
NetQ3_1: Q3.1 R3.2 | length 462.3
  Top Layer w10: Q3.1 1188.98,1172.24 1196.77,1180.04 1206.61,1180.04 1259.29,1232.72 1311.74,1232.72 1338.58,1259.56 1338.58,1423.23 R3.2
NetQ4_1: Q4.1 R4.2 | length 473.7
  Top Layer w10: R4.2 1292.24,1567.99 1292.24,1553.77 1312.24,1533.77 1312.24,1477.85 1366.14,1423.95 Q4.1
NetR1_1: R1.1 U2.15 | length 442.8
  Top Layer w10: U2.15 1090.01,1552.17 1094.18,1547.99 1164.17,1547.99 1178.39,1533.77 1178.39,1345.71 R1.1
NetR2_1: R2.1 U2.14 | length 255.1
  Top Layer w10: U2.14 1016.21,1502.17 1029.79,1515.75 v1(1062.99,1515.75) ; v1(1056.7,1418.8) 1064.23,1418.8 1085.39,1397.64 R2.1
  Bottom Layer w10: v1(1056.7,1418.8) 1059.85,1421.95 1059.85,1512.6 v1(1062.99,1515.75)
NetR3_1: R3.1 U2.13 | length 153
  Top Layer w10: U2.13 1016.73,1452.17 1044.81,1480.25 1116.07,1480.25 R3.1
NetR4_1: R4.1 U2.12 | length 481.2
  Top Layer w10: v1(925.2,1476.38) 925.2,1474.91 949.57,1450.54 949.57,1429.96 977.36,1402.17 U2.12 ; v1(935.04,1624.02) 940.97,1629.95 965.84,1629.95 1063.06,1629.96 1091.25,1601.77 1124.6,1601.77 R4.1
  Bottom Layer w10: v1(925.2,1476.38) 930.12,1481.3 930.12,1619.09 v1(935.04,1624.02)
NetR5_2: R5.2 U3.15 | length 250
  Top Layer w10: U3.15@1735.7,1599.41 1797.56,1599.41 1798.61,1600.46 1844.42,1600.46 1866.09,1578.79 1866.94,1578.79 1872.8,1572.93 1872.8,1523.57 1880.62,1515.75 R5.2
NetU1_1: U1.1 U4.20 | length 2520.4
  Top Layer w10: U4.20 2101.61,1160.28 2101.61,1553.93 2209.42,1661.74 2319.2,1661.74 2441.93,1784.47 2441.93,2061.56 2564.65,2184.29 2940.71,2184.29 U1.1
NetU1_2: U1.2 U4.22 | length 2417.3
  Bottom Layer w10: U4.22 1708.73,567.39 1708.73,1210.61 1767.06,1268.94 1936.99,1268.94 2768.05,2100 U1.2
NetU1_34: U1.34 U4.21 | length 1736.4
  Top Layer w10: U4.21 1731.32,376.94 1734.25,374.02 2156.42,374.02 cw(c2174.8,333.46) 2193.19,374.02 2197.22,374.02 2253.4,317.84 2253.4,203.73 2324.5,132.64 2557.64,132.64 U1.34
NetU1_36: U1.36 U3.2 | length 2266.9
  Top Layer w10: U3.2 1494.82,1598.69 1530.18,1598.69 1610.27,1518.6 ; 1610.28,1518.58 cw(c1603.19,1511.53) 1613.14,1512.59 ; 1613.14,1512.55 1618.93,1458.4 1626.9,1393.48 v1(1772.02,1223.69)
  Bottom Layer w10: v1(1772.02,1223.69) 1772.02,773.28 2156.36,388.93 2527.44,388.93 2538.51,400 U1.36
NetU1_50: U1.50 U2.2 | length 501.5
  Top Layer w10: U1.50 476.54,1551.54 476.54,1463.14 488.14,1451.54 654.29,1451.54 754.92,1552.17 U2.2
NetU1_52: U1.52 U2.1 | length 291.9
  Top Layer w10: U1.52 576.54,1551.54 704.29,1551.54 754.92,1602.17 U2.1
NetU1_59: U1.59 U4.15 | length 1225.5
  Bottom Layer w10: U1.59 576.54,1051.54 576.54,979.93 604.93,951.54 1392.87,951.54 U4.15
NetU1_61: U1.61 U4.14 | length 1066.2
  Bottom Layer w10: U1.61 1375.01,1000 1479.04,1104.03 1479.04,1137.7 U4.14
NetU1_63: U1.63 U3.3 | length 1840.2
  Top Layer w10: U3.3 1494.82,1573.1 1527.48,1573.1 1590.27,1510.31 1590.27,1380.97 1619.33,1351.91 1619.33,920.04 v1(1663.39,875.98)
  Bottom Layer w10: U1.63 637.69,900 668.61,869.07 671.54,866.14 679.83,866.14 1538.74,877.52 1538.8,877.52 1568.33,877.52 cw(c1574.8,833.46) 1581.28,877.52 1661.67,877.52 v1@1663.3,875.89
NetU1_71: U1.71 U3.4 | length 2038.4
  Top Layer w10: v1(1437.01,659.45) 1407.48,688.98 1407.48,734.69 1380.67,761.5 1380.67,836.92 1430.32,886.57 1464.87,886.57 1473.66,895.36 1473.66,970.78 1464.87,979.57 1413.34,979.57 1407.48,985.42 1407.48,1349.42 1482.04,1423.98 1527.77,1423.98 1540.59,1436.8 1540.59,1454.93 1540.59,1481.53 1540.59,1531.7 1524.79,1547.51 1494.82,1547.51 U3.4
  Bottom Layer w10: U1.71 906.63,500 961.07,554.45 1009.24,554.45 1130.05,675.26 1304.07,675.26 1319.89,659.45 v1(1437.01,659.45)
pads on no net: U1.0 U1.3 U1.4 U1.5 U1.7 U1.9 U1.10 U1.11 U1.12 U1.13 U1.14 U1.15 U1.17 U1.18 U1.21 U1.23 U1.24 U1.25 U1.26 U1.27 U1.28 U1.29 U1.30 U1.31 U1.32 U1.33 U1.35 U1.37 U1.38 U1.39 U1.40 U1.41 U1.42 U1.43 U1.44 U1.45 U1.46 U1.48 U1.49 U1.54 U1.55 U1.56 U1.57 U1.60 U1.62 U1.64 U1.65 U1.66 U1.67 U1.68 U1.69 U1.70 U1.72 U1.73 U1.74 U1.75 U1.76 U2.7 U2.9 U2.10 U2.11 U3.14 U4.3 U4.6 U4.7 U4.8 U4.9 U4.10 U4.11 U4.12 U4.16 U4.17 U4.18 U4.23 U4.24

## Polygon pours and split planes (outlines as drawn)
GND on Top Layer "GND_L01_P000" (solid, remove dead copper, pour order 0): 679.13,2234.25 2874.02,2234.25 2874.02,78.74 688.98,78.74
GND on Bottom Layer "GND_L02_P001" (solid, remove dead copper, pour order 1): 688.98,78.74 2874.02,78.74 2874.02,2253.94 679.13,2253.94

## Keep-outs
Keep-Out Layer:
  lines w78.74: 0,0 0,2300 3550,2300 3550,0 0,0

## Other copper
Top Layer:
  text "Debreczeni Laszlo A27" at 225,550 h60 r90
Bottom Layer:
  text "Debreczeni Laszlo A27" at 175,550 h60 r270

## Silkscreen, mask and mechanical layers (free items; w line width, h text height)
Mechanical 1:
  lines w10: 0,0 0,2300 3550,2300 3550,0 0,0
